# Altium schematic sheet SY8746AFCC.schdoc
size 127 x 101 mm
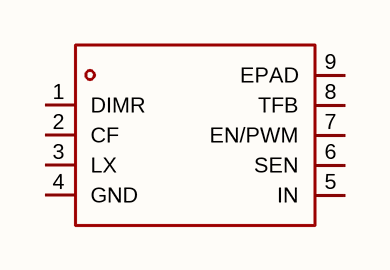
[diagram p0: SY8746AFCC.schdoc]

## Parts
U?  sy8746afcc  [SO-8_L4.9-W3.9-P1.27-LS6.0-BL-EP]  (value not drawn)

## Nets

Not connected (* = marked no-connect by the designer): U? 1(DIMR) 2(CF) 3(LX) 4(GND) 5(IN) 6(SEN) 7(EN/PWM) 8(TFB) 9(EPAD)

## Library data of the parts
U? = sy8746afcc: 功能类型:降压型;工作电压:12V~60V;输出电压:36V;输出电流:-;输出类型:-;; Manufacturer: Silergy(矽力杰); AddInBom: yes; ModelId: 756fba4e187a48c69a2c935cd5c4465b; ModelName: SO-8_L4.9-W3.9-H1.5-LS5.9-P1.27; ModelTransform: 240.39054,192.913,0,270,0,0,0.004,-0.002,0; Function: 降压型; Output Voltage: 36V; Frequency - Switching: 350kHz; Synchronous Rectifier: 否; Number of Outputs: 1; Topology: 降压式; Quiescent Current: 800uA; Switch tube (built-in/external): 内置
